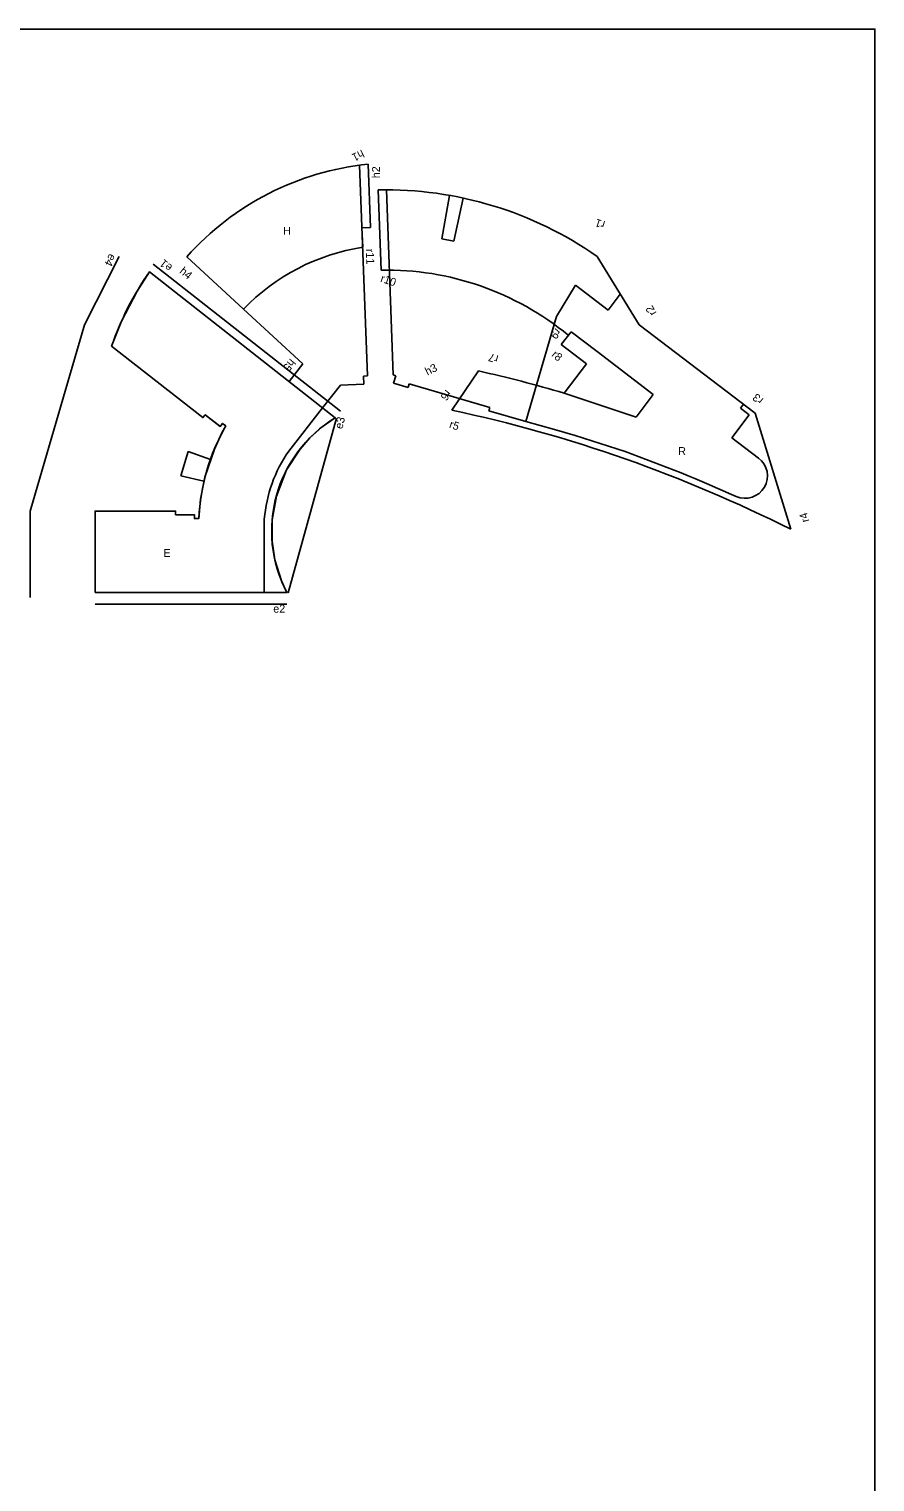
# Model space of a CAD drawing. Extents: x -4333 to -3435, y 16386 to 16556.
# Drawn here: x -3469 to -3435.1, y 16446.5 to 16504.7 of the extents above; entities that cross this region are included whole.
import ezdxf

# ---------------------------------------------------------------- set-up
doc = ezdxf.new("R2010")
doc.units = 0
for name, color, linetype in [('Level 1', 7, 'Continuous'), ('Level 43', 7, 'Continuous'), ('Level 44', 7, 'Continuous'), ('Level 45', 7, 'Continuous'), ('Level 5', 7, 'Continuous'), ('Level 60', 7, 'Continuous'), ('Level 7', 7, 'Continuous')]:
    doc.layers.add(name, color=color, linetype=linetype)

msp = doc.modelspace()

# ---------------------------------------------------------------- linework, layer by layer
at = {"layer": 'Level 1'}
msp.add_lwpolyline([(-3672.718, 16385.896), (-3435.118, 16385.896), (-3435.118, 16504.696), (-3672.718, 16504.696)], close=True, dxfattribs=at)
msp.add_lwpolyline([(-3672.718, 16385.896), (-3435.118, 16385.896), (-3435.118, 16504.696), (-3672.718, 16504.696)], close=True, dxfattribs=at)
msp.add_lwpolyline([(-3435.118, 16497.896), (-3435.118, 16457.896)], dxfattribs=at)
at = {"layer": 'Level 43'}
for p, q in [((-3455.318, 16496.757), (-3455.412, 16499.291)), ((-3455.664, 16496.734), (-3455.318, 16496.757)), ((-3455.628, 16495.96), (-3455.657, 16496.735)), ((-3462.667, 16495.584), (-3460.399, 16493.487))]:
    msp.add_line(p, q, dxfattribs=at)
msp.add_lwpolyline([(-3466.342, 16482.139), (-3466.342, 16485.406), (-3463.122, 16485.406), (-3463.122, 16485.254), (-3462.363, 16485.254), (-3462.365, 16485.102), (-3462.193, 16485.102), (-3462.119, 16485.878), (-3461.943, 16486.761), (-3461.566, 16487.886), (-3461.263, 16488.532), (-3461.11, 16488.812), (-3461.239, 16488.913), (-3461.333, 16488.794), (-3461.93, 16489.262), (-3462.024, 16489.143), (-3465.68, 16492.008), (-3465.289, 16492.999), (-3464.664, 16494.208), (-3464.169, 16494.979), (-3456.726, 16489.138), (-3457.251, 16488.774), (-3457.743, 16488.334), (-3458.138, 16487.886), (-3458.674, 16487.055), (-3459.085, 16486.004), (-3459.254, 16485.051), (-3459.256, 16484.2), (-3459.144, 16483.45), (-3458.865, 16482.572), (-3458.661, 16482.139)], close=True, dxfattribs=at)
for centre, radius, start, end in [((-3454.249, 16488.063), 11.288, 95.91362, 138.2247), ((-3454.364, 16487.684), 8.372, 98.68672, 136.123)]:
    msp.add_arc(centre, radius, start, end, dxfattribs=at)
at = {"layer": 'Level 44'}
for p, q in [((-3454.885, 16495.051), (-3455.005, 16498.258)), ((-3444.557, 16492.86), (-3446.246, 16495.596)), ((-3465.379, 16495.594), (-3466.769, 16492.862)), ((-3464.015, 16495.285), (-3456.519, 16489.403)), ((-3456.726, 16489.138), (-3464.169, 16494.979)), ((-3466.769, 16492.862), (-3468.946, 16485.406)), ((-3444.557, 16492.86), (-3439.911, 16489.321)), ((-3447.286, 16492.584), (-3447.68, 16492.066)), ((-3447.286, 16492.584), (-3446.24, 16491.787)), ((-3465.68, 16492.008), (-3462.024, 16489.143)), ((-3447.68, 16492.066), (-3446.666, 16491.294)), ((-3446.24, 16491.787), (-3443.992, 16490.075)), ((-3450.996, 16491.015), (-3452.06, 16489.443)), ((-3446.666, 16491.294), (-3447.555, 16490.126)), ((-3447.555, 16490.126), (-3444.684, 16489.166)), ((-3444.684, 16489.166), (-3443.992, 16490.075)), ((-3462.024, 16489.143), (-3461.93, 16489.262)), ((-3461.93, 16489.262), (-3461.333, 16488.794)), ((-3461.93, 16489.262), (-3461.366, 16488.82)), ((-3439.911, 16489.321), (-3438.492, 16484.674)), ((-3461.239, 16488.913), (-3461.333, 16488.794)), ((-3461.11, 16488.812), (-3461.239, 16488.913)), ((-3458.609, 16482.125), (-3456.674, 16489.124)), ((-3468.946, 16481.947), (-3468.946, 16485.406)), ((-3463.122, 16485.406), (-3466.342, 16485.406)), ((-3466.342, 16485.406), (-3466.342, 16482.139)), ((-3463.122, 16485.254), (-3463.122, 16485.406)), ((-3463.122, 16485.254), (-3462.363, 16485.254)), ((-3462.405, 16485.254), (-3463.122, 16485.254)), ((-3462.363, 16485.102), (-3462.363, 16485.254)), ((-3462.365, 16485.102), (-3462.193, 16485.102)), ((-3466.342, 16482.139), (-3458.661, 16482.139)), ((-3466.342, 16482.139), (-3459.567, 16482.139)), ((-3466.342, 16481.683), (-3458.661, 16481.683))]:
    msp.add_line(p, q, dxfattribs=at)
for centre, radius, start, end in [((-3454.689, 16483.557), 14.704, 54.95787, 91.23231), ((-3454.689, 16483.557), 11.495, 50.61297, 90.98028), ((-3454.249, 16488.063), 12.093, 145.11877, 160.96157), ((-3454.249, 16488.063), 12.093, 145.11877, 160.96157), ((-3463.763, 16434.462), 57.976, 73.76617, 77.27843), ((-3463.763, 16434.462), 56.213, 63.28422, 77.98335), ((-3453.95, 16484.708), 8.252, 150.17905, 177.26536), ((-3453.97, 16484.609), 5.302, 121.31825, 207.7677)]:
    msp.add_arc(centre, radius, start, end, dxfattribs=at)
at = {"layer": 'Level 45'}
msp.add_line((-3444.075, 16489.966), (-3443.992, 16490.075), dxfattribs=at)
at = {"layer": 'Level 60'}
msp.add_lwpolyline([(-3672.721, 16385.894), (-3435.121, 16385.894), (-3435.121, 16504.694), (-3672.721, 16504.694)], close=True, dxfattribs=at)
at = {"layer": 'Level 7'}
for p, q in [((-3455.436, 16490.811), (-3455.751, 16499.251)), ((-3454.404, 16490.85), (-3454.68, 16498.262)), ((-3452.148, 16498.04), (-3452.457, 16496.295)), ((-3451.978, 16496.206), (-3451.603, 16497.934)), ((-3452.457, 16496.295), (-3451.978, 16496.206)), ((-3447.868, 16493.193), (-3447.102, 16494.442)), ((-3447.102, 16494.442), (-3445.802, 16493.446)), ((-3445.802, 16493.446), (-3445.314, 16494.087)), ((-3460.399, 16493.487), (-3458.026, 16491.293)), ((-3449.096, 16488.99), (-3447.868, 16493.193)), ((-3458.577, 16490.591), (-3458.026, 16491.293)), ((-3457.231, 16489.535), (-3456.519, 16490.443)), ((-3456.519, 16490.443), (-3455.584, 16490.477)), ((-3455.596, 16490.805), (-3455.436, 16490.811)), ((-3455.584, 16490.477), (-3455.596, 16490.805)), ((-3454.404, 16490.85), (-3454.305, 16490.821)), ((-3454.305, 16490.821), (-3454.392, 16490.522)), ((-3454.392, 16490.522), (-3453.805, 16490.353)), ((-3453.805, 16490.353), (-3453.765, 16490.494)), ((-3453.765, 16490.494), (-3450.537, 16489.551)), ((-3458.591, 16487.802), (-3457.231, 16489.535)), ((-3450.575, 16489.422), (-3450.537, 16489.551)), ((-3450.575, 16489.422), (-3449.095, 16488.99)), ((-3440.15, 16489.249), (-3440.845, 16488.337)), ((-3440.384, 16489.681), (-3440.507, 16489.521)), ((-3440.507, 16489.521), (-3440.15, 16489.249)), ((-3447.95, 16488.669), (-3449.096, 16488.99)), ((-3447.126, 16488.422), (-3447.95, 16488.669)), ((-3445.116, 16487.782), (-3447.126, 16488.422)), ((-3440.845, 16488.337), (-3439.777, 16487.524)), ((-3462.62, 16487.782), (-3462.906, 16486.808)), ((-3461.724, 16487.462), (-3462.62, 16487.782)), ((-3462.906, 16486.808), (-3461.99, 16486.595)), ((-3459.567, 16482.139), (-3459.567, 16485.079))]:
    msp.add_line(p, q, dxfattribs=at)
for centre, radius, start, end in [((-3453.972, 16484.611), 5.614, 145.35745, 175.21129), ((-3465.657, 16430.599), 60.761, 65.72358, 70.24144), ((-3440.32, 16486.81), 0.897, 246.66677, 52.70031)]:
    msp.add_arc(centre, radius, start, end, dxfattribs=at)

# ---------------------------------------------------------------- texts
at = {"layer": 'Level 5'}
for s, height, rotation, p in [('h1', 0.3203, 206.53644, (-3455.67, 16499.882)), ('h2', 0.3203, 89.87956, (-3454.935, 16498.726)), ('H', 0.32, 359.99938, (-3458.819, 16496.46)), ('r1', 0.3203, 162.17286, (-3445.896, 16496.992)), ('e4', 0.3203, 242.6099, (-3465.761, 16495.73)), ('r11', 0.3203, 272.09039, (-3455.501, 16495.894)), ('e1', 0.3203, 140.76122, (-3463.222, 16495.203)), ('h4', 0.3203, 320.76122, (-3462.988, 16494.955)), ('r10', 0.3203, 341.17668, (-3454.942, 16494.589)), ('r2', 0.3203, 121.73913, (-3443.849, 16493.343)), ('r9', 0.3203, 229.61019, (-3447.899, 16492.748)), ('r7', 0.3203, 165.02752, (-3450.172, 16491.626)), ('r8', 0.3203, 319.61019, (-3448.091, 16491.622)), ('h5', 0.3203, 230.76122, (-3458.532, 16491.529)), ('h3', 0.3203, 26.36304, (-3453.037, 16490.824)), ('r6', 0.3203, 230.58546, (-3452.293, 16490.284)), ('r3', 0.3203, 140.56418, (-3439.557, 16489.891)), ('e3', 0.3203, 75.80474, (-3456.446, 16488.666)), ('r5', 0.3203, 341.0814, (-3452.187, 16488.749)), ('R', 0.32, 359.99938, (-3442.993, 16487.643)), ('r4', 0.3203, 105.94224, (-3437.743, 16485.004)), ('E', 0.32, 359.99938, (-3463.608, 16483.567)), ('e2', 0.3203, 359.99938, (-3459.207, 16481.337))]:
    msp.add_text(s, height=height, rotation=rotation, dxfattribs=at).set_placement(p)

doc.saveas('drawing.dxf')
